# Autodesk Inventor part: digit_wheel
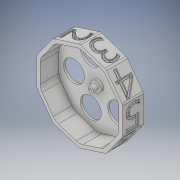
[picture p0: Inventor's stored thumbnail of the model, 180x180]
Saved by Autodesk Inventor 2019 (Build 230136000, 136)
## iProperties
Created: 2018-06
Part Number: digit_wheel
Material: Generic
Document SubType Name: Modeling
Designer: felldings
Density: 1 g/cm^3
Appearance: Default
Author: felldings
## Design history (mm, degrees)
sketch "Sketch1"
  geometry: L1 (0, 64.721)-(38.042, 52.361); L2 (38.042, 52.361)-(61.554, 20); L3 (61.554, 20)-(61.554, -20); L4 (61.554, -20)-(38.042, -52.361); L5 (38.042, -52.361)-(0, -64.721); L6 (0, -64.721)-(-38.042, -52.361); L7 (-38.042, -52.361)-(-61.554, -20); L8 (-61.554, -20)-(-61.554, 20); L9 (-61.554, 20)-(-38.042, 52.361); L10 (-38.042, 52.361)-(0, 64.721); L11 (0, -90.61)-(0, 90.61) reference; 2 further points
  constraints: 20 end point, 1 coincident, 1 point on line, 21 other
  dimensions: "d0" = 40 distance of L7.end L8.end; "d1" = 129.44272 distance of L5.end L1.start (derived)
extrude "baseplate" new body sketch "Sketch1" distance "d2" = 3; taper "d3" = 0 deg
sketch "Sketch2"
  geometry: L1 (-38.042, 52.361)-(-61.554, 20) reference; L2 (0, 64.721)-(-38.042, 52.361) reference; L3 (38.042, 52.361)-(0, 64.721) reference; L4 (61.554, 20)-(38.042, 52.361) reference; L5 (61.554, -20)-(61.554, 20) reference; L6 (38.042, -52.361)-(61.554, -20) reference; L7 (0, -64.721)-(38.042, -52.361) reference; L8 (-38.042, -52.361)-(0, -64.721) reference; L9 (-61.554, -20)-(-38.042, -52.361) reference; L10 (-61.554, 20)-(-61.554, -20) reference; L11 (0, 59.464)-(34.952, 48.107); L12 (34.952, 48.107)-(56.554, 18.375); L13 (56.554, 18.375)-(56.554, -18.375); L14 (56.554, -18.375)-(34.952, -48.107); L15 (34.952, -48.107)-(0, -59.464); L16 (0, -59.464)-(-34.952, -48.107); L17 (-34.952, -48.107)-(-56.554, -18.375); L18 (-56.554, -18.375)-(-56.554, 18.375); L19 (-56.554, 18.375)-(-34.952, 48.107); L20 (-34.952, 48.107)-(0, 59.464); 2 further points
  constraints: 20 end point, 1 coincident, 21 other
  dimensions: "d4" = 5 distance between parallel lines of L18 L10
extrude "outer_rim" join sketch "Sketch2" distance "d5" = 27; taper "d6" = 0 deg
sketch "Sketch3"
  geometry: C1 r 7.5 at (0, 0); 1 further point
  constraints: 1 centre point, 1 coincident
  dimensions: "d7" = 15 diameter of C1
extrude "mount_base" join sketch "Sketch3" distance "d8" = 3.5; taper "d9" = 0 deg
sketch "Sketch4"
  geometry: C1 r 3.95 at (0, 0); 1 further point
  constraints: 1 centre point, 1 coincident
  dimensions: "d10" = 7.9 diameter of C1
extrude "mount_stump" join sketch "Sketch4" distance "d11" = 7.5; taper "d12" = 0 deg
sketch "Sketch5"
  geometry: L1 (-1.41, 0.95)-(1.41, 0.95); A1 r 1.7 centre (0, 0) between (-1.41, 0.95) and (1.41, 0.95); 1 further point
  constraints: 2 end point, 2 point on circle, 1 centre point, 1 coincident, 1 horizontal
  dimensions: "d13" = 1.7 radius of A1; "d14" = 2.65 dimension on A1 L1
extrude "motor_hole" cut sketch "Sketch5" distance "d15" = 10; taper "d16" = 0 deg
sketch "Sketch6"
  geometry: A1 r 1.7 centre (0, 0) between (-1.41, 0.95) and (1.41, 0.95) reference; 2 further points
  constraints: 1 coincident
hole "magnet_hole" sketch "Sketch6" at (0, 0) diameter "d17" = 6.4; stored, may be unused: countersink angle "d21" = 90 deg, drill point angle "d23" = 0 deg; dims "d18" = 2, "d19" = 4, "d20" = 2, "d22" = 2.7
sketch "Sketch7"
  geometry: L1 (2.5, 37.5)-(28.764, 37.5); L2 (28.764, 37.5)-(28.764, -15.383); L3 (28.764, -15.383)-(2.5, -15.383); L4 (2.5, -15.383)-(2.5, 37.5); L5 (0, 40)-(0, 0) reference; L6 (0, 40)-(30, 40) reference; 1 further point
  constraints: 2 other
  dimensions: "d24" = 2.5 distance between parallel lines of L5 L4; "d25" = 2.5 distance between parallel lines of L6 L1
extrude "dig0" cut sketch "Sketch7" distance "d26" = 3; taper "d27" = 0 deg
sketch "Sketch8"
  geometry: L1 (2.5, 37.5)-(27.263, 37.5); L2 (27.263, 37.5)-(27.263, 3.913); L3 (27.263, 3.913)-(2.5, 3.913); L4 (2.5, 3.913)-(2.5, 37.5); L5 (0, 40)-(0, 0) reference; L6 (0, 40)-(30, 40) reference; 1 further point
  constraints: 2 other
  dimensions: "d28" = 2.5 distance between parallel lines of L5 L4; "d29" = 2.5 distance between parallel lines of L6 L1
extrude "dig1" cut sketch "Sketch8" distance "d30" = 3; taper "d31" = 0 deg
sketch "Sketch9"
  geometry: L1 (37.5, 27.5)-(37.5, 2.737); L2 (37.5, 2.737)-(1.705, 2.737); L3 (1.705, 2.737)-(1.705, 27.5); L4 (1.705, 27.5)-(37.5, 27.5); L5 (40, 30)-(0, 30) reference; L6 (40, 30)-(40, 0) reference; 1 further point
  constraints: 2 other
  dimensions: "d32" = 2.5 distance between parallel lines of L5 L4; "d33" = 2.5 distance between parallel lines of L6 L1
extrude "dig2" cut sketch "Sketch9" distance "d34" = 3; taper "d35" = 0 deg
sketch "Sketch10"
  geometry: L1 (37.5, 27.5)-(37.5, 2.737); L2 (37.5, 2.737)-(-3.944, 2.737); L3 (-3.944, 2.737)-(-3.944, 27.5); L4 (-3.944, 27.5)-(37.5, 27.5); L5 (40, 30)-(0, 30) reference; L6 (40, 30)-(40, 0) reference; 1 further point
  constraints: 2 other
  dimensions: "d36" = 2.5 distance between parallel lines of L5 L4; "d37" = 2.5 distance between parallel lines of L6 L1
extrude "dig3" cut sketch "Sketch10" distance "d38" = 3; taper "d39" = 0 deg
sketch "Sketch11"
  geometry: L1 (27.5, -37.5)-(2.737, -37.5); L2 (2.737, -37.5)-(2.737, -4.5); L3 (2.737, -4.5)-(27.5, -4.5); L4 (27.5, -4.5)-(27.5, -37.5); L5 (30, -40)-(30, 0) reference; L6 (30, -40)-(0, -40) reference; 1 further point
  constraints: 2 other
  dimensions: "d40" = 2.5 distance between parallel lines of L5 L4; "d41" = 2.5 distance between parallel lines of L6 L1
extrude "dig4" cut sketch "Sketch11" distance "d42" = 3; taper "d43" = 0 deg
sketch "Sketch12"
  geometry: L1 (-2.5, 2.5)-(-27.263, 2.5); L2 (-27.263, 2.5)-(-27.263, 36.195); L3 (-27.263, 36.195)-(-2.5, 36.195); L4 (-2.5, 36.195)-(-2.5, 2.5); L5 (0, 0)-(0, 40) reference; L6 (0, 0)-(-30, 0) reference; 1 further point
  constraints: 2 other
  dimensions: "d44" = 2.5 distance between parallel lines of L5 L4; "d45" = 2.5 distance between parallel lines of L6 L1
extrude "dig5" cut sketch "Sketch12" distance "d46" = 3; taper "d47" = 0 deg
sketch "Sketch13"
  geometry: L1 (27.5, -37.5)-(2.737, -37.5); L2 (2.737, -37.5)-(2.737, -3.19); L3 (2.737, -3.19)-(27.5, -3.19); L4 (27.5, -3.19)-(27.5, -37.5); L5 (30, -40)-(30, 0) reference; L6 (30, -40)-(0, -40) reference; 1 further point
  constraints: 2 other
  dimensions: "d48" = 2.5 distance between parallel lines of L5 L4; "d49" = 2.5 distance between parallel lines of L6 L1
extrude "dig6" cut sketch "Sketch13" distance "d50" = 3; taper "d51" = 0 deg
sketch "Sketch14"
  geometry: L1 (-37.5, 2.5)-(-37.5, 27.263); L2 (-37.5, 27.263)-(11.291, 27.263); L3 (11.291, 27.263)-(11.291, 2.5); L4 (11.291, 2.5)-(-37.5, 2.5); L5 (-40, 0)-(0, 0) reference; L6 (-40, 0)-(-40, 30) reference; 1 further point
  constraints: 2 other
  dimensions: "d52" = 2.5 distance between parallel lines of L5 L4; "d53" = 2.5 distance between parallel lines of L6 L1
extrude "dig7" cut sketch "Sketch14" distance "d54" = 3; taper "d55" = 0 deg
sketch "Sketch15"
  geometry: L1 (-37.5, 2.5)-(-37.5, 27.263); L2 (-37.5, 27.263)-(14.07, 27.263); L3 (14.07, 27.263)-(14.07, 2.5); L4 (14.07, 2.5)-(-37.5, 2.5); L5 (-40, 0)-(0, 0) reference; L6 (-40, 0)-(-40, 30) reference; 1 further point
  constraints: 2 other
  dimensions: "d56" = 2.5 distance between parallel lines of L5 L4; "d57" = 2.5 distance between parallel lines of L6 L1
extrude "dig8" cut sketch "Sketch15" distance "d58" = 3; taper "d59" = 0 deg
sketch "Sketch16"
  geometry: L1 (2.5, 37.5)-(27.263, 37.5); L2 (27.263, 37.5)-(27.263, -14.951); L3 (27.263, -14.951)-(2.5, -14.951); L4 (2.5, -14.951)-(2.5, 37.5); L5 (0, 40)-(0, 0) reference; L6 (0, 40)-(30, 40) reference; 1 further point
  constraints: 2 other
  dimensions: "d60" = 2.5 distance between parallel lines of L5 L4; "d61" = 2.5 distance between parallel lines of L6 L1
extrude "dig9" cut sketch "Sketch16" distance "d62" = 3; taper "d63" = 0 deg
fillet "Fillet1" dims "d64" = 15
fillet "Fillet2" dims "d65" = 5
sketch "Sketch17"
  geometry: L1 (-35, 0)-(-10.816, 33.287); L2 (-10.816, 33.287)-(28.316, 20.572); L3 (28.316, 20.572)-(28.316, -20.572); L4 (28.316, -20.572)-(-10.816, -33.287); L5 (-10.816, -33.287)-(-35, 0); L6 (-86.175, 0)-(86.175, 0) reference; A1 r 1.7 centre (0, 0) between (-1.41, 0.95) and (1.41, 0.95) reference; 7 further points
  constraints: 10 end point, 6 coincident, 1 point on line, 11 other
  dimensions: "d66" = 35 distance of point (0, 0) L1.start
hole "Hole2" sketch "Sketch17" at (-35, 0), (-10.816, 33.287), (28.316, 20.572), (28.316, -20.572), (-10.816, -33.287) diameter "d67" = 30; stored, may be unused: countersink angle "d71" = 90 deg, drill point angle "d73" = 0 deg; dims "d68" = 2, "d69" = 4, "d70" = 2, "d72" = 3
fillet "Fillet3" dims "d74" = 1.5
body "Solid1"
